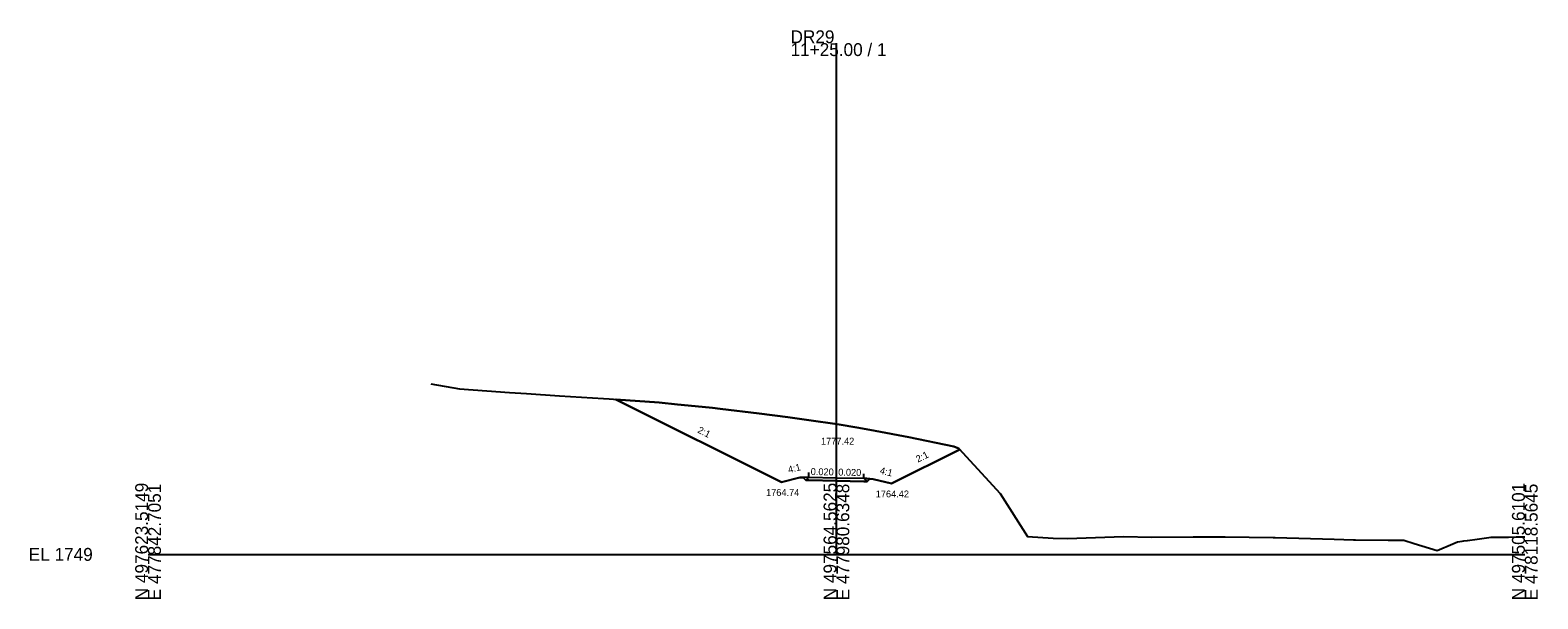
# Model space of a CAD drawing. Extents: x -26 to 303, y -10 to 4734.
# Drawn here: x -25.7 to 302.8, y 2490.3 to 2614.3 of the extents above; entities that cross this region are included whole.
import ezdxf

# ---------------------------------------------------------------- set-up
doc = ezdxf.new("R2010")
doc.units = 0
for name, color, linetype in [('Exist Cross Section Cell', 7, 'Continuous'), ('Exist XS Center Line Elevation Label', 7, 'Continuous'), ('Exist XS Ground Line', 7, 'Continuous'), ('Prop XS Ditch Slope Text', 7, 'Continuous'), ('Prop XS Ditch Standard Text', 7, 'Continuous'), ('Prop XS Dump Level', 7, 'Continuous'), ('Prop XS Earthwork Shape', 7, 'Continuous'), ('Prop XS EOT Tick Mark', 7, 'Continuous'), ('Prop XS Finish Grade', 7, 'Continuous'), ('Prop XS Finish Grade Earthwork', 7, 'Continuous'), ('Prop XS Finish Grade Pavement', 7, 'Continuous'), ('Prop XS Pvmt Edge Slope', 7, 'Continuous'), ('Prop XS SE Text', 7, 'Continuous'), ('Prop XS Shoulder Borrow Shape', 7, 'Continuous'), ('Prop XS Side Slope Text', 7, 'Continuous'), ('Prop XS Subgrade Earthwork', 7, 'Continuous')]:
    doc.layers.add(name, color=color, linetype=linetype)

msp = doc.modelspace()

# ---------------------------------------------------------------- linework, layer by layer
at = {"layer": 'Exist Cross Section Cell'}
for p, q in [((150, 2500), (150, 2611.42)), ((0, 2500), (150, 2500)), ((150, 2500), (300, 2500))]:
    msp.add_line(p, q, dxfattribs=at)
at = {"layer": 'Exist XS Ground Line'}
msp.add_lwpolyline([(61.64, 2537.14), (67.87, 2536.08), (73.81, 2535.65), (78.75, 2535.29), (82.44, 2535.07), (89.63, 2534.54), (99.25, 2533.99), (100.5, 2533.9), (101.44, 2533.83), (111.38, 2533.07), (115.37, 2532.64), (122.26, 2532.02), (122.99, 2531.94), (124.7, 2531.72), (133.14, 2530.71), (139.43, 2529.88), (144.01, 2529.28), (150.15, 2528.4), (154.89, 2527.6), (158.43, 2526.94), (165.77, 2525.53), (175.6, 2523.51), (176.64, 2523.11), (185.71, 2513.29), (191.6, 2503.91), (197.24, 2503.54), (200.32, 2503.47), (212.52, 2503.92), (218.72, 2503.75), (227.76, 2503.84), (234.7, 2503.81), (245.16, 2503.67), (245.6, 2503.66), (258.46, 2503.3), (262.68, 2503.18), (263.13, 2503.18), (270.23, 2503.11), (273.63, 2503.1), (275.87, 2502.37), (280.88, 2500.83), (284.34, 2502.32), (285.32, 2502.71), (286.34, 2502.87), (286.73, 2502.93), (287.52, 2503.04), (289.59, 2503.32), (292.67, 2503.75), (293.31, 2503.77), (293.68, 2503.77), (295.15, 2503.78), (295.7, 2503.78), (296.41, 2503.78), (298.44, 2503.8), (300, 2503.83)], dxfattribs=at)
at = {"layer": 'Prop XS Dump Level'}
for p, q in [((144, 2516.82), (150, 2516.7)), ((150, 2516.7), (156, 2516.58))]:
    msp.add_line(p, q, dxfattribs=at)
at = {"layer": 'Prop XS Earthwork Shape'}
for points in [[(158, 2516.42), (162, 2515.42), (176.88, 2522.86), (176.64, 2523.11), (175.6, 2523.51), (165.77, 2525.53), (158.43, 2526.94), (154.89, 2527.6), (150.15, 2528.4), (144.01, 2529.28), (139.43, 2529.88), (133.14, 2530.71), (124.7, 2531.72), (122.99, 2531.94), (122.26, 2532.02), (115.37, 2532.64), (111.38, 2533.07), (101.9, 2533.79), (138, 2515.74), (142, 2516.74), (142.74, 2516.77), (143.35, 2516.16), (144, 2516.15), (150, 2516.03), (156, 2515.91), (156.68, 2515.9), (157.26, 2516.48)], [(156, 2515.91), (150, 2516.03), (144, 2516.15), (143.35, 2516.16), (142.74, 2516.77), (142, 2516.74), (138, 2515.74), (101.9, 2533.79), (111.38, 2533.07), (115.37, 2532.64), (122.26, 2532.02), (122.99, 2531.94), (124.7, 2531.72), (133.14, 2530.71), (139.43, 2529.88), (144.01, 2529.28), (150.15, 2528.4), (154.89, 2527.6), (158.43, 2526.94), (165.77, 2525.53), (175.6, 2523.51), (176.64, 2523.11), (176.88, 2522.86), (162, 2515.42), (158, 2516.42), (157.26, 2516.48), (156.68, 2515.9)]]:
    msp.add_lwpolyline(points, close=True, dxfattribs=at)
at = {"layer": 'Prop XS EOT Tick Mark'}
for p, q in [((144, 2516.82), (144, 2517.82)), ((156, 2516.58), (156, 2517.58))]:
    msp.add_line(p, q, dxfattribs=at)
at = {"layer": 'Prop XS Finish Grade'}
for p, q in [((144, 2516.82), (142.74, 2516.77)), ((156, 2516.58), (157.26, 2516.48))]:
    msp.add_line(p, q, dxfattribs=at)
at = {"layer": 'Prop XS Finish Grade Earthwork'}
for p, q in [((138, 2515.74), (101.9, 2533.79)), ((162, 2515.42), (176.88, 2522.86)), ((142, 2516.74), (138, 2515.74)), ((142.74, 2516.77), (142, 2516.74)), ((157.26, 2516.48), (158, 2516.42)), ((158, 2516.42), (162, 2515.42))]:
    msp.add_line(p, q, dxfattribs=at)
at = {"layer": 'Prop XS Finish Grade Pavement'}
for p, q in [((144, 2516.82), (150, 2516.7)), ((150, 2516.7), (156, 2516.58))]:
    msp.add_line(p, q, dxfattribs=at)
at = {"layer": 'Prop XS Pvmt Edge Slope'}
for p, q in [((144, 2516.82), (143.35, 2516.16)), ((156, 2516.58), (156.68, 2515.9))]:
    msp.add_line(p, q, dxfattribs=at)
at = {"layer": 'Prop XS Shoulder Borrow Shape'}
for points in [[(144, 2516.82), (142.74, 2516.77), (143.35, 2516.16)], [(156.68, 2515.9), (157.26, 2516.48), (156, 2516.58)]]:
    msp.add_lwpolyline(points, close=True, dxfattribs=at)
at = {"layer": 'Prop XS Subgrade Earthwork'}
for p, q in [((143.35, 2516.16), (142.74, 2516.77)), ((144, 2516.15), (143.35, 2516.16)), ((150, 2516.03), (144, 2516.15)), ((156, 2515.91), (150, 2516.03)), ((156, 2515.91), (156.68, 2515.9)), ((156.68, 2515.9), (157.26, 2516.48))]:
    msp.add_line(p, q, dxfattribs=at)

# ---------------------------------------------------------------- texts
at = {"layer": 'Exist Cross Section Cell'}
for s, p in [('DR29', (140, 2611.42)), ('11+25.00 / 1', (140, 2608.62)), ('EL 1749', (-26, 2498.6))]:
    msp.add_text(s, height=2.8, dxfattribs=at).set_placement(p)
for s, p in [('N 497623.5149', (0, 2490)), ('E 477842.7051', (2.8, 2490)), ('N 497564.5625', (150, 2490)), ('E 477980.6348', (152.8, 2490)), ('N 497505.6101', (300, 2490)), ('E 478118.5645', (302.8, 2490))]:
    msp.add_text(s, height=2.8, rotation=90, dxfattribs=at).set_placement(p)
at = {"layer": 'Exist XS Center Line Elevation Label'}
msp.add_text('1777.42', height=1.5, dxfattribs=at).set_placement((146.63, 2523.92))
at = {"layer": 'Prop XS Ditch Slope Text'}
for rotation, p in [(14.0362, (139.64, 2517.69)), (345.9638, (159.33, 2517.63))]:
    msp.add_text('4:1', height=1.5, rotation=rotation, dxfattribs=at).set_placement(p)
at = {"layer": 'Prop XS Ditch Standard Text'}
for s, p in [('1764.74', (134.66, 2512.74)), ('1764.42', (158.56, 2512.42))]:
    msp.add_text(s, height=1.5, dxfattribs=at).set_placement(p)
at = {"layer": 'Prop XS Dump Level'}
for p in [(142, 2516.7), (158, 2516.38)]:
    msp.add_text('Case1', height=0.04, dxfattribs=at).set_placement(p)
at = {"layer": 'Prop XS SE Text'}
for p in [(144.38, 2517.31), (150.38, 2517.19)]:
    msp.add_text('0.020', height=1.5, rotation=358.8542, dxfattribs=at).set_placement(p)
at = {"layer": 'Prop XS Side Slope Text'}
for rotation, p in [(333.4349, (119.6, 2526.61)), (26.5651, (167.76, 2519.97))]:
    msp.add_text('2:1', height=1.5, rotation=rotation, dxfattribs=at).set_placement(p)

doc.saveas('drawing.dxf')
